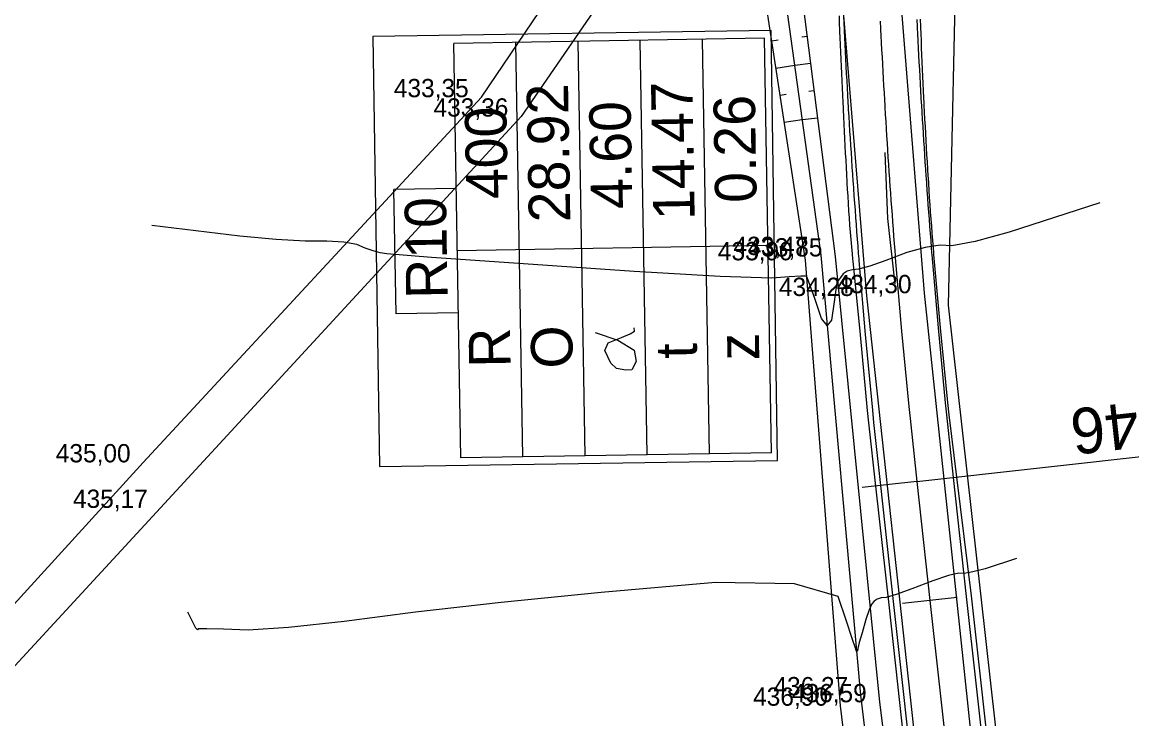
# Model space of a CAD drawing. Extents: x -574342 to -507939, y -1144044 to -1123894.
# Drawn here: x -508587.2 to -508526.6, y -1143874.6 to -1143836.5 of the extents above; entities that cross this region are included whole.
import ezdxf

# ---------------------------------------------------------------- set-up
doc = ezdxf.new("R2010")
doc.units = 0
for name, color, linetype in [('01_PARCELY_NAVRH_PC', 7, 'Continuous'), ('1000', 7, 'Continuous'), ('18', 7, 'Continuous'), ('21', 7, 'Continuous'), ('23', 7, 'Continuous'), ('55', 7, 'Continuous'), ('6', 7, 'Continuous'), ('60', 7, 'Continuous'), ('61', 7, 'Continuous'), ('Level 255', 7, 'Continuous'), ('SO 101_popis oblouku', 7, 'Continuous'), ('tab', 7, 'Continuous'), ('VRST VEDL', 7, 'Continuous')]:
    doc.layers.add(name, color=color, linetype=linetype)

msp = doc.modelspace()

# ---------------------------------------------------------------- linework, layer by layer
msp.add_lwpolyline([(-508545.946, -1143860.431), (-508546.295, -1143836.913), (-508568.065, -1143837.236), (-508567.716, -1143860.754)], close=True)
at = {"layer": '01_PARCELY_NAVRH_PC'}
msp.add_lwpolyline([(-508540.36, -1143791.5), (-508536.1, -1143827.99), (-508536.63, -1143851.93), (-508527.92, -1143929.74), (-508538.84, -1143929.88), (-508538.33, -1143908.31), (-508542.5, -1143873.84), (-508544.43, -1143849.48), (-508547.15, -1143831.66), (-508549.26, -1143826.59), (-508553.2, -1143819.26), (-508550.74, -1143812.56), (-508547.51, -1143799.72)], dxfattribs=at)
msp.add_lwpolyline([(-508540.36, -1143791.5), (-508536.1, -1143827.99), (-508536.63, -1143851.93), (-508527.92, -1143929.74), (-508538.84, -1143929.88), (-508538.33, -1143908.31), (-508542.5, -1143873.84), (-508544.43, -1143849.48), (-508547.15, -1143831.66), (-508549.26, -1143826.59), (-508553.2, -1143819.26), (-508550.74, -1143812.56), (-508547.51, -1143799.72)], dxfattribs=at)
at = {"layer": '1000'}
for points in [[(-508542.589, -1143836.115), (-508542.573, -1143836.51), (-508542.558, -1143836.905), (-508542.555, -1143836.976), (-508542.541, -1143837.299), (-508542.525, -1143837.694), (-508542.508, -1143838.088), (-508542.491, -1143838.483), (-508542.474, -1143838.877), (-508542.456, -1143839.272), (-508542.439, -1143839.667), (-508542.42, -1143840.061), (-508542.402, -1143840.456), (-508542.383, -1143840.85), (-508542.37, -1143841.128), (-508542.364, -1143841.245), (-508542.345, -1143841.639), (-508542.326, -1143842.034), (-508542.306, -1143842.428), (-508542.286, -1143842.823), (-508542.265, -1143843.217), (-508542.245, -1143843.612), (-508542.224, -1143844.006), (-508542.203, -1143844.401), (-508542.181, -1143844.795), (-508542.159, -1143845.189), (-508542.154, -1143845.278), (-508542.137, -1143845.584), (-508542.115, -1143845.978), (-508542.092, -1143846.373), (-508542.069, -1143846.767), (-508542.041, -1143847.161), (-508542.009, -1143847.555), (-508541.976, -1143847.948), (-508541.943, -1143848.342), (-508541.91, -1143848.736), (-508541.877, -1143849.129), (-508541.852, -1143849.423), (-508541.843, -1143849.523), (-508541.431, -1143853.558), (-508541.046, -1143857.696), (-508540.979, -1143858.372), (-508540.595, -1143861.827), (-508539.872, -1143868.33), (-508536.224, -1143901.692)], [(-508542.351, -1143836.104), (-508542.333, -1143836.499), (-508542.314, -1143836.893), (-508542.311, -1143836.965), (-508542.295, -1143837.287), (-508542.275, -1143837.681), (-508542.255, -1143838.075), (-508542.234, -1143838.469), (-508542.214, -1143838.864), (-508542.192, -1143839.258), (-508542.171, -1143839.652), (-508542.149, -1143840.046), (-508542.126, -1143840.44), (-508542.104, -1143840.834), (-508542.087, -1143841.111), (-508542.08, -1143841.228), (-508542.057, -1143841.622), (-508542.033, -1143842.016), (-508542.009, -1143842.41), (-508541.984, -1143842.804), (-508541.959, -1143843.197), (-508541.933, -1143843.591), (-508541.907, -1143843.985), (-508541.881, -1143844.379), (-508541.854, -1143844.773), (-508541.827, -1143845.166), (-508541.821, -1143845.255), (-508541.8, -1143845.56), (-508541.772, -1143845.954), (-508541.744, -1143846.348), (-508541.715, -1143846.741), (-508541.686, -1143847.135), (-508541.657, -1143847.528), (-508541.627, -1143847.922), (-508541.597, -1143848.315), (-508541.567, -1143848.709), (-508541.536, -1143849.102), (-508541.512, -1143849.396), (-508541.504, -1143849.496), (-508541.161, -1143853.534), (-508540.766, -1143857.668), (-508540.698, -1143858.343), (-508540.329, -1143861.797), (-508539.607, -1143868.301), (-508535.903, -1143901.656)], [(-508538.337, -1143836.309), (-508538.319, -1143836.699), (-508538.315, -1143836.77), (-508538.3, -1143837.089), (-508538.28, -1143837.48), (-508538.26, -1143837.87), (-508538.24, -1143838.26), (-508538.219, -1143838.65), (-508538.198, -1143839.04), (-508538.177, -1143839.431), (-508538.155, -1143839.821), (-508538.133, -1143840.211), (-508538.11, -1143840.601), (-508538.094, -1143840.876), (-508538.087, -1143840.991), (-508538.064, -1143841.381), (-508538.04, -1143841.771), (-508538.016, -1143842.161), (-508537.992, -1143842.551), (-508537.967, -1143842.941), (-508537.942, -1143843.331), (-508537.916, -1143843.721), (-508537.89, -1143844.111), (-508537.864, -1143844.501), (-508537.837, -1143844.89), (-508537.831, -1143844.978), (-508537.81, -1143845.28), (-508537.782, -1143845.67), (-508537.754, -1143846.06), (-508537.726, -1143846.449), (-508537.697, -1143846.839), (-508537.668, -1143847.229), (-508537.639, -1143847.618), (-508537.609, -1143848.008), (-508537.579, -1143848.398), (-508537.548, -1143848.787), (-508537.525, -1143849.078), (-508537.517, -1143849.177), (-508537.177, -1143853.175), (-508536.786, -1143857.267), (-508536.719, -1143857.936), (-508536.354, -1143861.356), (-508535.632, -1143867.86), (-508531.927, -1143901.214)], [(-508538.151, -1143836.3), (-508538.137, -1143836.69), (-508538.134, -1143836.761), (-508538.122, -1143837.081), (-508538.107, -1143837.471), (-508538.091, -1143837.861), (-508538.075, -1143838.251), (-508538.058, -1143838.642), (-508538.041, -1143839.032), (-508538.024, -1143839.422), (-508538.006, -1143839.812), (-508537.987, -1143840.203), (-508537.968, -1143840.593), (-508537.955, -1143840.867), (-508537.949, -1143840.983), (-508537.929, -1143841.373), (-508537.909, -1143841.763), (-508537.888, -1143842.153), (-508537.867, -1143842.543), (-508537.845, -1143842.933), (-508537.823, -1143843.323), (-508537.8, -1143843.713), (-508537.777, -1143844.103), (-508537.753, -1143844.493), (-508537.729, -1143844.883), (-508537.724, -1143844.971), (-508537.704, -1143845.273), (-508537.679, -1143845.663), (-508537.654, -1143846.052), (-508537.628, -1143846.442), (-508537.602, -1143846.832), (-508537.573, -1143847.222), (-508537.542, -1143847.611), (-508537.511, -1143848.001), (-508537.48, -1143848.39), (-508537.448, -1143848.779), (-508537.424, -1143849.07), (-508537.416, -1143849.169), (-508537.06, -1143853.164), (-508536.654, -1143857.254), (-508536.583, -1143857.922), (-508536.169, -1143861.335), (-508535.36, -1143867.829), (-508531.663, -1143901.185)]]:
    msp.add_lwpolyline(points, dxfattribs=at)
at = {"layer": '21'}
msp.add_lwpolyline([(-508540.335, -1143836.404), (-508540.316, -1143836.796), (-508540.313, -1143836.867), (-508540.297, -1143837.188), (-508540.278, -1143837.58), (-508540.258, -1143837.973), (-508540.237, -1143838.365), (-508540.216, -1143838.757), (-508540.195, -1143839.149), (-508540.174, -1143839.541), (-508540.152, -1143839.933), (-508540.13, -1143840.325), (-508540.107, -1143840.717), (-508540.091, -1143840.993), (-508540.084, -1143841.109), (-508540.06, -1143841.501), (-508540.037, -1143841.893), (-508540.012, -1143842.285), (-508539.988, -1143842.677), (-508539.963, -1143843.069), (-508539.937, -1143843.461), (-508539.912, -1143843.853), (-508539.886, -1143844.245), (-508539.859, -1143844.637), (-508539.832, -1143845.028), (-508539.826, -1143845.117), (-508539.805, -1143845.42), (-508539.777, -1143845.812), (-508539.749, -1143846.204), (-508539.721, -1143846.595), (-508539.692, -1143846.987), (-508539.663, -1143847.379), (-508539.633, -1143847.77), (-508539.603, -1143848.162), (-508539.573, -1143848.553), (-508539.542, -1143848.945), (-508539.519, -1143849.237), (-508539.511, -1143849.336), (-508539.169, -1143853.354), (-508538.776, -1143857.468), (-508538.708, -1143858.14), (-508538.342, -1143861.577), (-508537.619, -1143868.08), (-508533.915, -1143901.435)], dxfattribs=at)
at = {"layer": '23'}
for points in [[(-508538.342, -1143861.577), (-508511.507, -1143858.596)], [(-508538.342, -1143861.577), (-508541.323, -1143861.908)]]:
    msp.add_lwpolyline(points, dxfattribs=at)
at = {"layer": '55'}
for points in [[(-508548.61, -1143735.08), (-508548.65, -1143740.56), (-508547.87, -1143747.22), (-508545.1, -1143768.03), (-508541.4, -1143799.09), (-508540.43, -1143820.16), (-508537.93, -1143851.28), (-508535.31, -1143876.1), (-508531.43, -1143907.19), (-508528.41, -1143930.89), (-508527.67, -1143936.89)], [(-508548.61, -1143735.08), (-508548.65, -1143740.56), (-508547.87, -1143747.22), (-508545.1, -1143768.03), (-508541.4, -1143799.09), (-508540.43, -1143820.16), (-508537.93, -1143851.28), (-508535.31, -1143876.1), (-508531.43, -1143907.19), (-508528.41, -1143930.89), (-508527.67, -1143936.89)], [(-508562.14, -1143840.56), (-508550.22, -1143822.92), (-508543.59, -1143814.54)], [(-508562.14, -1143840.56), (-508550.22, -1143822.92), (-508543.59, -1143814.54)], [(-508543.03, -1143827.63), (-508545.43, -1143824.71), (-508548.76, -1143825.29), (-508559.97, -1143841.62)], [(-508543.03, -1143827.63), (-508545.43, -1143824.71), (-508548.76, -1143825.29), (-508559.97, -1143841.62)], [(-508543.03, -1143827.63), (-508541.09, -1143851.43), (-508538.33, -1143876.72), (-508534.84, -1143908), (-508533.38, -1143923.57), (-508535.55, -1143929.18), (-508537.07, -1143931.02), (-508540.64, -1143933.27), (-508556.35, -1143937.53), (-508584.9, -1143944.5), (-508606.58, -1143950.85), (-508637.73, -1143960.32), (-508651.63, -1143964)], [(-508543.03, -1143827.63), (-508541.09, -1143851.43), (-508538.33, -1143876.72), (-508534.84, -1143908), (-508533.38, -1143923.57), (-508535.55, -1143929.18), (-508537.07, -1143931.02), (-508540.64, -1143933.27), (-508556.35, -1143937.53), (-508584.9, -1143944.5), (-508606.58, -1143950.85), (-508637.73, -1143960.32), (-508651.63, -1143964)], [(-508562.14, -1143840.56), (-508580.62, -1143860.53), (-508608.32, -1143890.94), (-508631.28, -1143916.57), (-508659.69, -1143947.85), (-508668.29, -1143960.82), (-508673.01, -1143966.59), (-508682.95, -1143976.88)], [(-508562.14, -1143840.56), (-508580.62, -1143860.53), (-508608.32, -1143890.94), (-508631.28, -1143916.57), (-508659.69, -1143947.85), (-508668.29, -1143960.82), (-508673.01, -1143966.59), (-508682.95, -1143976.88)], [(-508663.15, -1143966.99), (-508664.02, -1143966.02), (-508666.03, -1143962.35), (-508657.38, -1143949.21), (-508629.98, -1143918.5), (-508606.59, -1143892.21), (-508579.68, -1143863.02), (-508559.97, -1143841.62)], [(-508663.15, -1143966.99), (-508664.02, -1143966.02), (-508666.03, -1143962.35), (-508657.38, -1143949.21), (-508629.98, -1143918.5), (-508606.59, -1143892.21), (-508579.68, -1143863.02), (-508559.97, -1143841.62)]]:
    msp.add_lwpolyline(points, dxfattribs=at)
at = {"layer": '6'}
msp.add_lwpolyline([(-508536.128, -1143867.915), (-508539.11, -1143868.246)], dxfattribs=at)
at = {"layer": '60'}
for points in [[(-508549.26, -1143826.59), (-508547.68, -1143825.48), (-508545.19, -1143830.56), (-508542.8, -1143849.27), (-508540.38, -1143873.65), (-508536.01, -1143908.3), (-508536.27, -1143928.5), (-508537.27, -1143930.57), (-508540.7, -1143933.07), (-508556.38, -1143937.09), (-508584.83, -1143944.26), (-508606.44, -1143950.52), (-508637.67, -1143959.86), (-508663.03, -1143966.64)], [(-508549.26, -1143826.59), (-508547.68, -1143825.48), (-508545.19, -1143830.56), (-508542.8, -1143849.27), (-508540.38, -1143873.65), (-508536.01, -1143908.3), (-508536.27, -1143928.5), (-508537.27, -1143930.57), (-508540.7, -1143933.07), (-508556.38, -1143937.09), (-508584.83, -1143944.26), (-508606.44, -1143950.52), (-508637.67, -1143959.86), (-508663.03, -1143966.64)], [(-508663.03, -1143966.64), (-508658.41, -1143964.52), (-508638.63, -1143958.83), (-508606.36, -1143949.47), (-508584.73, -1143942.7), (-508556.52, -1143935.72), (-508542.25, -1143932.55), (-508537.69, -1143930.36), (-508536.92, -1143928.11), (-508537.11, -1143908.45), (-508541.39, -1143873.27), (-508543.57, -1143849.19), (-508546.08, -1143831.04), (-508548.45, -1143826.2)], [(-508663.03, -1143966.64), (-508658.41, -1143964.52), (-508638.63, -1143958.83), (-508606.36, -1143949.47), (-508584.73, -1143942.7), (-508556.52, -1143935.72), (-508542.25, -1143932.55), (-508537.69, -1143930.36), (-508536.92, -1143928.11), (-508537.11, -1143908.45), (-508541.39, -1143873.27), (-508543.57, -1143849.19), (-508546.08, -1143831.04), (-508548.45, -1143826.2)], [(-508542.25, -1143932.55), (-508538.84, -1143929.88), (-508537.68, -1143927.96), (-508538.33, -1143908.31), (-508542.5, -1143873.84), (-508544.43, -1143849.48), (-508547.15, -1143831.66), (-508549.26, -1143826.59)], [(-508542.25, -1143932.55), (-508538.84, -1143929.88), (-508537.68, -1143927.96), (-508538.33, -1143908.31), (-508542.5, -1143873.84), (-508544.43, -1143849.48), (-508547.15, -1143831.66), (-508549.26, -1143826.59)]]:
    msp.add_lwpolyline(points, dxfattribs=at)
at = {"layer": '61'}
for p, q in [((-508546.261, -1143837.483), (-508545.912, -1143837.429)), ((-508546.261, -1143837.483), (-508545.912, -1143837.429)), ((-508544.338, -1143837.234), (-508544.627, -1143837.271)), ((-508544.338, -1143837.234), (-508544.627, -1143837.271)), ((-508546.035, -1143838.965), (-508545.006, -1143838.808)), ((-508546.035, -1143838.965), (-508545.006, -1143838.808)), ((-508544.147, -1143838.721), (-508545.003, -1143838.831)), ((-508544.147, -1143838.721), (-508545.003, -1143838.831)), ((-508545.809, -1143840.448), (-508545.473, -1143840.397)), ((-508545.809, -1143840.448), (-508545.473, -1143840.397)), ((-508543.957, -1143840.209), (-508544.237, -1143840.245)), ((-508543.957, -1143840.209), (-508544.237, -1143840.245)), ((-508545.582, -1143841.931), (-508544.595, -1143841.78)), ((-508545.582, -1143841.931), (-508544.595, -1143841.78)), ((-508543.767, -1143841.697), (-508544.592, -1143841.803)), ((-508543.767, -1143841.697), (-508544.592, -1143841.803))]:
    msp.add_line(p, q, dxfattribs=at)
at = {"layer": 'SO 101_popis oblouku'}
for p, q in [((-508546.654, -1143837.337), (-508563.652, -1143837.625)), ((-508559.869, -1143860.231), (-508560.252, -1143837.567)), ((-508556.469, -1143860.173), (-508556.853, -1143837.51)), ((-508553.07, -1143860.116), (-508553.453, -1143837.452)), ((-508549.67, -1143860.058), (-508550.054, -1143837.395)), ((-508546.271, -1143860.001), (-508546.654, -1143837.337)), ((-508563.268, -1143860.288), (-508563.652, -1143837.625)), ((-508563.518, -1143845.557), (-508566.917, -1143845.615)), ((-508566.802, -1143852.414), (-508566.917, -1143845.615)), ((-508546.463, -1143848.669), (-508563.46, -1143848.957)), ((-508563.403, -1143852.356), (-508566.802, -1143852.414)), ((-508546.271, -1143860.001), (-508563.268, -1143860.288))]:
    msp.add_line(p, q, dxfattribs=at)
msp.add_lwpolyline([(-508555.926, -1143853.436), (-508554.675, -1143853.85), (-508553.787, -1143854.385), (-508553.68, -1143855.009), (-508553.908, -1143855.468), (-508554.241, -1143855.48), (-508554.749, -1143855.39), (-508555.062, -1143855.099), (-508555.386, -1143854.414), (-508555.202, -1143854), (-508554.483, -1143853.694), (-508554, -1143853.501), (-508553.777, -1143853.348), (-508553.781, -1143853.166)], dxfattribs=at)
at = {"layer": 'tab'}
msp.add_lwpolyline([(-508540.077, -1143843.582), (-508539.938, -1143847.197), (-508539.539, -1143850.792)], dxfattribs=at)
at = {"layer": 'VRST VEDL'}
for points in [[(-508528.328, -1143846.336), (-508533.282, -1143847.936), (-508535.152, -1143848.456), (-508536.413, -1143848.695), (-508537.067, -1143848.654), (-508537.887, -1143848.774), (-508538.873, -1143849.055), (-508540.025, -1143849.498), (-508540.907, -1143849.802), (-508541.519, -1143849.968), (-508541.861, -1143849.996), (-508542.141, -1143850.079), (-508542.358, -1143850.217), (-508542.513, -1143850.411), (-508542.621, -1143850.557), (-508542.683, -1143850.656), (-508542.698, -1143850.707), (-508542.757, -1143851.073), (-508542.861, -1143851.754), (-508543.009, -1143852.751), (-508543.235, -1143853.053), (-508543.539, -1143852.66), (-508543.92, -1143851.572), (-508544.182, -1143850.825), (-508544.323, -1143850.42), (-508544.344, -1143850.356), (-508544.674, -1143850.342), (-508545.312, -1143850.377), (-508546.259, -1143850.461), (-508549.083, -1143850.367), (-508553.783, -1143850.093), (-508560.361, -1143849.64), (-508564.868, -1143849.317), (-508567.302, -1143849.124), (-508567.665, -1143849.062), (-508568.062, -1143848.957), (-508568.492, -1143848.809), (-508568.956, -1143848.618), (-508569.657, -1143848.492), (-508570.594, -1143848.432), (-508571.768, -1143848.436), (-508573.351, -1143848.344), (-508575.344, -1143848.155), (-508580.148, -1143847.582)], [(-508532.891, -1143865.79), (-508534.608, -1143866.344), (-508535.274, -1143866.523), (-508535.749, -1143866.603), (-508536.033, -1143866.585), (-508536.603, -1143866.72), (-508537.46, -1143867.007), (-508538.605, -1143867.447), (-508539.458, -1143867.75), (-508540.02, -1143867.916), (-508540.29, -1143867.945), (-508540.509, -1143868.012), (-508540.675, -1143868.117), (-508540.788, -1143868.258), (-508540.935, -1143868.597), (-508541.117, -1143869.131), (-508541.332, -1143869.862), (-508541.481, -1143870.388), (-508541.565, -1143870.711), (-508541.583, -1143870.829), (-508541.609, -1143870.865), (-508541.646, -1143870.819), (-508541.691, -1143870.689), (-508541.87, -1143870.155), (-508542.184, -1143869.217), (-508542.631, -1143867.875), (-508545.015, -1143867.166), (-508549.333, -1143867.092), (-508555.588, -1143867.651), (-508561.056, -1143868.196), (-508565.738, -1143868.726), (-508569.634, -1143869.241), (-508572.681, -1143869.568), (-508574.881, -1143869.705), (-508576.232, -1143869.652), (-508577.147, -1143869.631), (-508577.625, -1143869.641), (-508577.665, -1143869.682), (-508577.746, -1143869.598), (-508577.867, -1143869.388), (-508578.189, -1143868.716)]]:
    msp.add_lwpolyline(points, dxfattribs=at)

# ---------------------------------------------------------------- texts
at = {"layer": '18'}
msp.add_text('KT0+843.46', height=2.5, rotation=186.33699, dxfattribs=at).set_placement((-508511.838, -1143855.615))
at = {"layer": 'Level 255'}
for s, p in [('433,35', (-508566.925, -1143840.56)), ('433,36', (-508564.755, -1143841.62)), ('433,90', (-508549.215, -1143849.48)), ('433,47', (-508548.355, -1143849.19)), ('433,85', (-508547.585, -1143849.27)), ('434,30', (-508542.715, -1143851.28)), ('434,28', (-508545.875, -1143851.43)), ('435,00', (-508585.405, -1143860.53)), ('435,17', (-508584.465, -1143863.02)), ('436,27', (-508546.175, -1143873.27)), ('436,59', (-508545.165, -1143873.65)), ('436,90', (-508547.285, -1143873.84))]:
    msp.add_text(s, height=1, dxfattribs=at).set_placement(p)
at = {"layer": 'SO 101_popis oblouku'}
for s, height, p in [('28.92', 2.2667, (-508557.275, -1143847.382)), ('14.47', 2.2667, (-508550.476, -1143847.267)), ('0.26', 2.2667, (-508547.091, -1143846.319)), ('400', 2.2667, (-508560.696, -1143846.117)), ('4.60', 2.2667, (-508553.886, -1143846.656)), ('R10', 2.2667, (-508563.983, -1143851.565)), ('R', 2.267, (-508560.54, -1143855.331)), ('O', 2.267, (-508557.139, -1143855.381)), ('z', 2.267, (-508546.945, -1143854.939)), ('t', 2.267, (-508550.347, -1143854.834))]:
    msp.add_text(s, height=height, rotation=90.96454, dxfattribs=at).set_placement(p)

doc.saveas('drawing.dxf')
